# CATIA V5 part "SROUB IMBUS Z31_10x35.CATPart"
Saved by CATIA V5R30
Part number: SROUB IMBUS Z31/10x35
Bounding box of the stored display mesh (mm): x -10 to 35, y -8 to 8, z -8 to 8
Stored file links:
  C:\Users\ondra\Desktop\PŘÍLOHA P III\CATIA\SROUB IMBUS Z31_10x35.CATPart
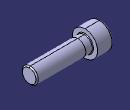
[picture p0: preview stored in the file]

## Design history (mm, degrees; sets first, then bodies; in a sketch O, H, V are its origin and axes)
Set1
  DatumSurface1 to DatumSurface30 "Z31/10x3"
  Join1: Elements (DatumSurface1; DatumSurface2; DatumSurface3; DatumSurface4; DatumSurface5; DatumSurface6; DatumSurface7; DatumSurface8; DatumSurface9; DatumSurface10; DatumSurface11; DatumSurface12; DatumSurface13; DatumSurface14; DatumSurface16; DatumSurface17; DatumSurface18; DatumSurface19; DatumSurface20; DatumSurface21; DatumSurface22; DatumSurface23; DatumSurface24; DatumSurface25; DatumSurface26; DatumSurface27; DatumSurface28; DatumSurface29; DatumSurface30)
Body1 (main body)
  CloseSurface1: CloseElement Join1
